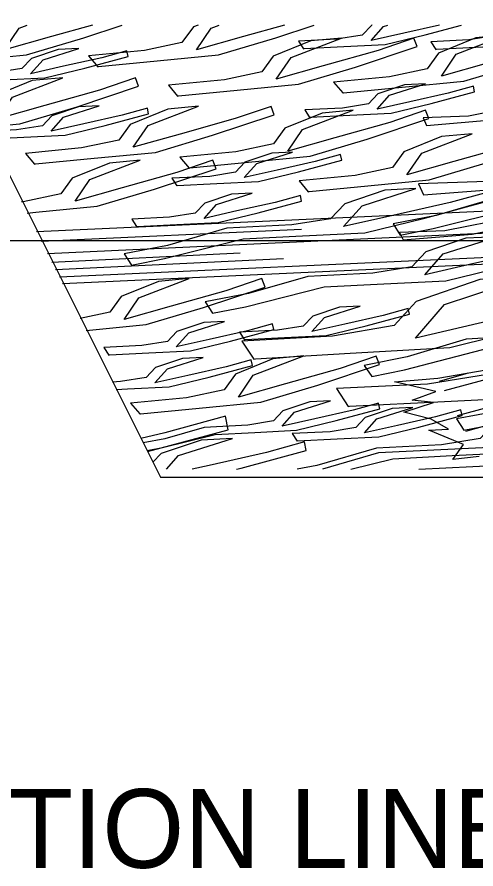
# Model space of a CAD drawing. Extents: x 1578769 to 1579225, y 724002 to 724828.
# Drawn here: x 1578874.36 to 1578877.28, y 724532.99 to 724538.4 of the extents above; entities that cross this region are included whole.
import ezdxf

# ---------------------------------------------------------------- set-up
doc = ezdxf.new("R2010")
doc.units = 0
for name, color, linetype in [('1', 7, 'Continuous'), ('G-ANNO-SYMB', 7, 'Continuous'), ('Old_Level_1', 7, 'Continuous'), ('Old_Level_41', 7, 'Continuous'), ('R_Fin Surface', 7, 'Continuous')]:
    doc.layers.add(name, color=color, linetype=linetype)

msp = doc.modelspace()

# ---------------------------------------------------------------- linework, layer by layer
at = {"layer": 'G-ANNO-SYMB'}
for p, q in [((1578877.0342, 724536.1057), (1578885.5756, 724537.5547)), ((1578874.4853, 724537.0347), (1578877.6371, 724537.1793)), ((1578874.5161, 724536.9737), (1578876.1682, 724537.0499)), ((1578874.5556, 724536.8955), (1578877.6246, 724537.0394)), ((1578874.5833, 724536.8408), (1578875.779, 724536.8994)), ((1578874.6065, 724536.7949), (1578876.0539, 724536.8636)), ((1578874.6306, 724536.7471), (1578877.5578, 724536.8825)), ((1578874.6516, 724536.7055), (1578877.5317, 724536.8379))]:
    msp.add_line(p, q, dxfattribs=at)
for points in [[(1578873.9421, 724538.1098), (1578874.033, 724538.1186), (1578874.4229, 724538.1563), (1578874.7854, 724538.2648), (1578875.0296, 724538.3458)], [(1578874.8405, 724538.3458), (1578874.5802, 724538.2725), (1578874.2817, 724538.1886), (1578874.3756, 724538.3263), (1578874.4264, 724538.3458)], [(1578875.511, 724538.3458), (1578875.4813, 724538.3337), (1578875.4091, 724538.2349), (1578875.1713, 724538.1843), (1578874.8157, 724538.15)], [(1578874.8157, 724538.15), (1578874.8742, 724538.081), (1578874.8796, 724538.0827), (1578875.2518, 724538.1186), (1578875.6417, 724538.1563), (1578876.0043, 724538.2648), (1578876.2485, 724538.3458)], [(1578876.0593, 724538.3458), (1578875.7991, 724538.2725), (1578875.5006, 724538.1886), (1578875.5944, 724538.3263), (1578875.6452, 724538.3458)], [(1578876.1497, 724538.2428), (1578876.1804, 724538.1953), (1578876.1842, 724538.1962), (1578876.4356, 724538.209), (1578876.699, 724538.2224), (1578876.9527, 724538.2836), (1578877.1825, 724538.3458)], [(1578876.616, 724538.3458), (1578876.6136, 724538.345), (1578876.5539, 724538.2815), (1578876.39, 724538.255), (1578876.1497, 724538.2428)], [(1578877.0436, 724538.3458), (1578876.8173, 724538.2949), (1578876.6091, 724538.248), (1578876.6879, 724538.3367), (1578876.7166, 724538.3458)], [(1578876.9894, 724538.239), (1578877.02, 724538.1914), (1578877.0238, 724538.1923), (1578877.2753, 724538.2051), (1578877.5387, 724538.2185), (1578877.7923, 724538.2797), (1578878.0365, 724538.3458)], [(1578877.4672, 724538.3458), (1578877.4533, 724538.3411), (1578877.3936, 724538.2776), (1578877.2296, 724538.2512), (1578876.9894, 724538.239)], [(1578876.3712, 724537.9835), (1578876.4297, 724537.9145), (1578876.4351, 724537.9162), (1578876.8073, 724537.9521), (1578877.1973, 724537.9898), (1578877.5598, 724538.0983), (1578877.9509, 724538.228), (1578877.9304, 724538.2811), (1578877.7028, 724538.204), (1578877.3546, 724538.1061), (1578877.0561, 724538.0221), (1578877.1499, 724538.1598), (1578877.4702, 724538.2826), (1578877.2752, 724538.2638), (1578877.0368, 724538.1672), (1578876.9646, 724538.0684), (1578876.7268, 724538.0178), (1578876.3712, 724537.9835)], [(1578875.3226, 724537.9641), (1578875.3811, 724537.8951), (1578875.3865, 724537.8968), (1578875.7587, 724537.9328), (1578876.1486, 724537.9704), (1578876.5112, 724538.079), (1578876.9023, 724538.2086), (1578876.8818, 724538.2618), (1578876.6542, 724538.1847), (1578876.306, 724538.0867), (1578876.0075, 724538.0027), (1578876.1013, 724538.1404), (1578876.4216, 724538.2633), (1578876.2266, 724538.2444), (1578875.9881, 724538.1479), (1578875.916, 724538.049), (1578875.6782, 724537.9985), (1578875.3226, 724537.9641)], [(1578873.9891, 724538.0317), (1578874.0197, 724537.9842), (1578874.0235, 724537.9851), (1578874.2749, 724537.9979), (1578874.5383, 724538.0113), (1578874.792, 724538.0725), (1578875.0672, 724538.1469), (1578875.0599, 724538.1829), (1578874.8996, 724538.1384), (1578874.6567, 724538.0838), (1578874.4484, 724538.0369), (1578874.5272, 724538.1256), (1578874.7545, 724538.1976), (1578874.6228, 724538.1909), (1578874.4529, 724538.1339), (1578874.3933, 724538.0704), (1578874.2293, 724538.0439), (1578873.9891, 724538.0317)], [(1578874.1509, 724537.6966), (1578874.3803, 724537.7188), (1578874.7429, 724537.8273), (1578875.134, 724537.957), (1578875.1135, 724538.0101), (1578874.8859, 724537.933), (1578874.5376, 724537.835), (1578874.2391, 724537.7511), (1578874.333, 724537.8888), (1578874.6533, 724538.0116), (1578874.4583, 724537.9928), (1578874.2198, 724537.8962), (1578874.1477, 724537.7974), (1578874.1046, 724537.7882)], [(1578876.1887, 724537.807), (1578876.2193, 724537.7594), (1578876.2231, 724537.7604), (1578876.4745, 724537.7732), (1578876.7379, 724537.7865), (1578876.9916, 724537.8478), (1578877.2668, 724537.9222), (1578877.2595, 724537.9581), (1578877.0992, 724537.9137), (1578876.8563, 724537.859), (1578876.648, 724537.8122), (1578876.7268, 724537.9008), (1578876.9541, 724537.9728), (1578876.8224, 724537.9661), (1578876.6525, 724537.9091), (1578876.5929, 724537.8457), (1578876.4289, 724537.8192), (1578876.1887, 724537.807)], [(1578874.1881, 724537.6228), (1578874.4044, 724537.6338), (1578874.6678, 724537.6471), (1578874.9215, 724537.7084), (1578875.1967, 724537.7828), (1578875.1894, 724537.8187), (1578875.029, 724537.7743), (1578874.7861, 724537.7197), (1578874.5779, 724537.6728), (1578874.6567, 724537.7614), (1578874.884, 724537.8334), (1578874.7523, 724537.8268), (1578874.5824, 724537.7698), (1578874.5227, 724537.7063), (1578874.3588, 724537.6798), (1578874.1643, 724537.6699)], [(1578874.4151, 724537.5313), (1578874.4736, 724537.4623), (1578874.479, 724537.464), (1578874.8512, 724537.4999), (1578875.2411, 724537.5376), (1578875.6037, 724537.6461), (1578875.9948, 724537.7758), (1578875.9743, 724537.8289), (1578875.7467, 724537.7518), (1578875.3984, 724537.6539), (1578875.1, 724537.5699), (1578875.1938, 724537.7076), (1578875.5141, 724537.8304), (1578875.3191, 724537.8116), (1578875.0806, 724537.715), (1578875.0085, 724537.6162), (1578874.7707, 724537.5656), (1578874.4151, 724537.5313)], [(1578875.3961, 724537.5073), (1578875.4546, 724537.4382), (1578875.46, 724537.4399), (1578875.8322, 724537.4759), (1578876.2222, 724537.5135), (1578876.5847, 724537.6221), (1578876.9758, 724537.7517), (1578876.9553, 724537.8049), (1578876.7277, 724537.7278), (1578876.3795, 724537.6298), (1578876.081, 724537.5459), (1578876.1749, 724537.6836), (1578876.4951, 724537.8064), (1578876.3001, 724537.7875), (1578876.0617, 724537.691), (1578875.9896, 724537.5922), (1578875.7517, 724537.5416), (1578875.3961, 724537.5073)], [(1578876.1524, 724537.3571), (1578876.211, 724537.2881), (1578876.2164, 724537.2897), (1578876.5886, 724537.3257), (1578876.9785, 724537.3634), (1578877.341, 724537.4719), (1578877.7322, 724537.6016), (1578877.7117, 724537.6547), (1578877.4841, 724537.5776), (1578877.1358, 724537.4796), (1578876.8373, 724537.3957), (1578876.9312, 724537.5334), (1578877.2514, 724537.6562), (1578877.0565, 724537.6374), (1578876.818, 724537.5408), (1578876.7459, 724537.442), (1578876.508, 724537.3914), (1578876.1524, 724537.3571)], [(1578875.3451, 724537.3733), (1578875.3758, 724537.3258), (1578875.3796, 724537.3267), (1578875.631, 724537.3395), (1578875.8944, 724537.3529), (1578876.1481, 724537.4141), (1578876.4233, 724537.4886), (1578876.416, 724537.5245), (1578876.2556, 724537.48), (1578876.0127, 724537.4254), (1578875.8045, 724537.3785), (1578875.8833, 724537.4672), (1578876.1106, 724537.5392), (1578875.9789, 724537.5325), (1578875.809, 724537.4755), (1578875.7493, 724537.412), (1578875.5854, 724537.3855), (1578875.3451, 724537.3733)], [(1578874.4255, 724537.153), (1578874.4818, 724537.1584), (1578874.8717, 724537.1961), (1578875.2343, 724537.3046), (1578875.6254, 724537.4343), (1578875.6049, 724537.4874), (1578875.3773, 724537.4103), (1578875.029, 724537.3123), (1578874.7306, 724537.2284), (1578874.8244, 724537.3661), (1578875.1447, 724537.4889), (1578874.9497, 724537.4701), (1578874.7112, 724537.3735), (1578874.6391, 724537.2747), (1578874.4013, 724537.2241), (1578874.3901, 724537.223)], [(1578876.749, 724537.0847), (1578876.7952, 724537.013), (1578877.0036, 724537.0545), (1578877.5043, 724537.1797), (1578877.8815, 724537.1989), (1578878.2766, 724537.2189), (1578878.6571, 724537.3108), (1578879.0699, 724537.4224), (1578879.0589, 724537.4763), (1578878.8184, 724537.4097), (1578878.4541, 724537.3277), (1578878.1418, 724537.2574), (1578878.2599, 724537.3904), (1578878.6008, 724537.4984), (1578878.4033, 724537.4883), (1578878.1485, 724537.4028), (1578878.059, 724537.3076), (1578877.813, 724537.2679), (1578877.4, 724537.2469), (1578877.0231, 724537.1371), (1578876.749, 724537.0847)], [(1578875.0426, 724536.8938), (1578875.0888, 724536.8221), (1578875.2972, 724536.8636), (1578875.798, 724536.9888), (1578876.1751, 724537.008), (1578876.5702, 724537.028), (1578876.9507, 724537.1199), (1578877.3635, 724537.2315), (1578877.3526, 724537.2854), (1578877.1121, 724537.2188), (1578876.7477, 724537.1368), (1578876.4354, 724537.0665), (1578876.5535, 724537.1995), (1578876.8945, 724537.3075), (1578876.6969, 724537.2974), (1578876.4421, 724537.212), (1578876.3526, 724537.1167), (1578876.1067, 724537.077), (1578875.6936, 724537.056), (1578875.3167, 724536.9462), (1578875.0426, 724536.8938)], [(1578875.0898, 724537.1139), (1578875.1204, 724537.0664), (1578875.1242, 724537.0673), (1578875.3756, 724537.0801), (1578875.639, 724537.0935), (1578875.8927, 724537.1547), (1578876.1679, 724537.2291), (1578876.1606, 724537.265), (1578876.0003, 724537.2206), (1578875.7573, 724537.166), (1578875.5491, 724537.1191), (1578875.6279, 724537.2078), (1578875.8552, 724537.2798), (1578875.7235, 724537.2731), (1578875.5536, 724537.2161), (1578875.4939, 724537.1526), (1578875.33, 724537.1261), (1578875.0898, 724537.1139)], [(1578875.5573, 724536.5889), (1578875.6035, 724536.5172), (1578875.8119, 724536.5587), (1578876.3126, 724536.6839), (1578876.6898, 724536.703), (1578877.0849, 724536.7231), (1578877.4654, 724536.815), (1578877.8782, 724536.9266), (1578877.8672, 724536.9805), (1578877.6267, 724536.9139), (1578877.2624, 724536.8319), (1578876.95, 724536.7616), (1578877.0682, 724536.8946), (1578877.4091, 724537.0026), (1578877.2116, 724536.9925), (1578876.9568, 724536.907), (1578876.8673, 724536.8118), (1578876.6213, 724536.7721), (1578876.2082, 724536.7511), (1578875.8314, 724536.6413), (1578875.5573, 724536.5889)], [(1578874.8018, 724536.4083), (1578875.1828, 724536.4451), (1578875.5453, 724536.5536), (1578875.9365, 724536.6833), (1578875.9159, 724536.7364), (1578875.6883, 724536.6593), (1578875.3401, 724536.5614), (1578875.0416, 724536.4774), (1578875.1355, 724536.6151), (1578875.4557, 724536.7379), (1578875.2608, 724536.7191), (1578875.0223, 724536.6225), (1578874.9502, 724536.5237), (1578874.7635, 724536.484)], [(1578875.7893, 724536.3396), (1578875.8657, 724536.2259), (1578875.8748, 724536.2282), (1578876.4774, 724536.2628), (1578877.1087, 724536.2989), (1578877.7137, 724536.4498), (1578878.3695, 724536.6327), (1578878.3498, 724536.7187), (1578877.9678, 724536.6097), (1578877.3882, 724536.4748), (1578876.8914, 724536.3591), (1578877.0749, 724536.5731), (1578877.616, 724536.7493), (1578877.3003, 724536.7313), (1578876.8962, 724536.5919), (1578876.7569, 724536.4386), (1578876.365, 724536.3726), (1578875.7893, 724536.3396)], [(1578876.5656, 724536.1865), (1578876.6136, 724536.115), (1578876.8209, 724536.1579), (1578877.3184, 724536.2863), (1578877.6951, 724536.3079), (1578878.0896, 724536.3305), (1578878.4677, 724536.4248), (1578878.8776, 724536.5391), (1578878.8653, 724536.5929), (1578878.6265, 724536.5247), (1578878.2643, 724536.4404), (1578877.9538, 724536.3681), (1578878.0685, 724536.5018), (1578878.4067, 724536.612), (1578878.2094, 724536.6007), (1578877.9568, 724536.5136), (1578877.8697, 724536.4178), (1578877.6248, 724536.3765), (1578877.2123, 724536.3529), (1578876.8383, 724536.2406), (1578876.5656, 724536.1865)], [(1578875.7751, 724536.3966), (1578875.8057, 724536.349), (1578875.8095, 724536.35), (1578876.0609, 724536.3627), (1578876.3243, 724536.3761), (1578876.578, 724536.4374), (1578876.8532, 724536.5118), (1578876.8459, 724536.5477), (1578876.6856, 724536.5033), (1578876.4427, 724536.4486), (1578876.2344, 724536.4018), (1578876.3132, 724536.4904), (1578876.5405, 724536.5624), (1578876.4088, 724536.5557), (1578876.2389, 724536.4987), (1578876.1793, 724536.4352), (1578876.0153, 724536.4088), (1578875.7751, 724536.3966)], [(1578877.1581, 724535.8691), (1578877.9126, 724536.073), (1578878.518, 724536.213), (1578878.8249, 724536.3238), (1578879.0076, 724536.3655), (1578879.3403, 724536.4158), (1578879.5398, 724536.4872)], [(1578874.9136, 724536.2993), (1578874.9442, 724536.2517), (1578874.948, 724536.2527), (1578875.1994, 724536.2654), (1578875.4628, 724536.2788), (1578875.7165, 724536.3401), (1578875.9917, 724536.4145), (1578875.9844, 724536.4504), (1578875.8241, 724536.406), (1578875.5811, 724536.3513), (1578875.3729, 724536.3045), (1578875.4517, 724536.3931), (1578875.679, 724536.4651), (1578875.5473, 724536.4584), (1578875.3774, 724536.4014), (1578875.3177, 724536.338), (1578875.1538, 724536.3115), (1578874.9136, 724536.2993)], [(1578876.3905, 724536.0387), (1578876.464, 724535.9246), (1578876.4731, 724535.9268), (1578877.0766, 724535.9575), (1578877.7087, 724535.9896), (1578878.3175, 724536.1366), (1578878.978, 724536.3152), (1578878.9605, 724536.4014), (1578878.5757, 724536.2948), (1578877.9927, 724536.1636), (1578877.493, 724536.0512), (1578877.682, 724536.2639), (1578878.2275, 724536.4367), (1578877.9115, 724536.4207), (1578877.5038, 724536.2839), (1578877.3605, 724536.1315), (1578876.967, 724536.068), (1578876.3905, 724536.0387)], [(1578877.2106, 724535.769), (1578877.7614, 724535.9235), (1578878.6223, 724536.1425), (1578878.9606, 724536.2065), (1578879.6231, 724536.3903)], [(1578874.9913, 724536.0333), (1578875.064, 724536.037), (1578875.3274, 724536.0504), (1578875.5811, 724536.1116), (1578875.8563, 724536.1861), (1578875.849, 724536.222), (1578875.6886, 724536.1775), (1578875.4457, 724536.1229), (1578875.2375, 724536.076), (1578875.3163, 724536.1647), (1578875.5436, 724536.2367), (1578875.4119, 724536.23), (1578875.242, 724536.173), (1578875.1823, 724536.1095), (1578875.0183, 724536.0831), (1578874.9674, 724536.0805)], [(1578875.0827, 724535.9469), (1578875.1412, 724535.8779), (1578875.1466, 724535.8796), (1578875.5188, 724535.9155), (1578875.9087, 724535.9532), (1578876.2713, 724536.0617), (1578876.6624, 724536.1914), (1578876.6419, 724536.2445), (1578876.4143, 724536.1674), (1578876.066, 724536.0695), (1578875.7676, 724535.9855), (1578875.8614, 724536.1232), (1578876.1817, 724536.246), (1578875.9867, 724536.2272), (1578875.7482, 724536.1306), (1578875.6761, 724536.0318), (1578875.4383, 724535.9812), (1578875.0827, 724535.9469)], [(1578877.1522, 724535.8462), (1578877.1984, 724535.7744), (1578877.4068, 724535.816), (1578877.9076, 724535.9411), (1578878.2847, 724535.9603), (1578878.6798, 724535.9804), (1578879.0603, 724536.0722), (1578879.4731, 724536.1839), (1578879.4622, 724536.2377), (1578879.2217, 724536.1711), (1578878.8573, 724536.0891), (1578878.545, 724536.0188), (1578878.6631, 724536.1518), (1578879.0041, 724536.2598), (1578878.8065, 724536.2498), (1578878.5517, 724536.1643), (1578878.4622, 724536.0691), (1578878.2163, 724536.0294), (1578877.8032, 724536.0084), (1578877.4263, 724535.8986), (1578877.1522, 724535.8462)], [(1578875.1874, 724535.6451), (1578875.2865, 724535.6649), (1578875.6204, 724535.7483), (1578875.8718, 724535.7611), (1578876.1352, 724535.7745), (1578876.3889, 724535.8357), (1578876.6641, 724535.9101), (1578876.6568, 724535.946), (1578876.4964, 724535.9016), (1578876.2535, 724535.847), (1578876.0453, 724535.8001), (1578876.1241, 724535.8888), (1578876.3514, 724535.9608), (1578876.2197, 724535.9541), (1578876.0498, 724535.8971), (1578875.9901, 724535.8336), (1578875.8262, 724535.8071), (1578875.5508, 724535.7931), (1578875.2995, 724535.7199), (1578875.1628, 724535.6938)], [(1578876.1088, 724535.7532), (1578876.1394, 724535.7056), (1578876.1432, 724535.7066), (1578876.3947, 724535.7193), (1578876.6581, 724535.7327), (1578876.9117, 724535.794), (1578877.1869, 724535.8684), (1578877.1796, 724535.9043), (1578877.0193, 724535.8599), (1578876.7764, 724535.8052), (1578876.5682, 724535.7584), (1578876.6469, 724535.847), (1578876.8742, 724535.919), (1578876.7425, 724535.9123), (1578876.5727, 724535.8553), (1578876.513, 724535.7918), (1578876.349, 724535.7654), (1578876.1088, 724535.7532)], [(1578876.4805, 724535.5275), (1578876.7474, 724535.5942), (1578877.1245, 724535.6134), (1578877.5196, 724535.6334), (1578877.9001, 724535.7253), (1578878.3129, 724535.837), (1578878.302, 724535.8908), (1578878.0615, 724535.8242), (1578877.6971, 724535.7422), (1578877.3848, 724535.6719), (1578877.5029, 724535.8049), (1578877.8439, 724535.9129), (1578877.6463, 724535.9028), (1578877.3915, 724535.8174), (1578877.302, 724535.7221), (1578877.0561, 724535.6824), (1578876.643, 724535.6615), (1578876.2662, 724535.5516), (1578876.1397, 724535.5275)], [(1578875.1904, 724535.6392), (1578875.7027, 724535.7777), (1578875.6852, 724535.8639), (1578875.3004, 724535.7573), (1578875.148, 724535.723)], [(1578875.3106, 724535.5274), (1578875.3879, 724535.6143), (1578875.7288, 724535.7223), (1578875.5313, 724535.7123), (1578875.2765, 724535.6268), (1578875.2246, 724535.5716)], [(1578875.7548, 724535.5274), (1578875.7851, 724535.5347), (1578876.1978, 724535.6464), (1578876.1869, 724535.7002), (1578875.9464, 724535.6336), (1578875.582, 724535.5516), (1578875.4744, 724535.5274)]]:
    msp.add_lwpolyline(points, dxfattribs=at)
for points in [[(1578876.9622, 724537.7091), (1578877.4018, 724537.7464), (1578877.6447, 724537.7967), (1578877.9763, 724537.8823), (1578878.2274, 724537.8966), (1578878.4904, 724537.9117), (1578878.7425, 724537.9746), (1578879.0158, 724538.0508), (1578879.0075, 724538.0866), (1578878.8484, 724538.0412), (1578878.6069, 724537.985), (1578878.3999, 724537.9368), (1578878.4764, 724538.0259), (1578878.7018, 724538.0994), (1578878.5703, 724538.0918), (1578878.4019, 724538.0338), (1578878.3438, 724537.9699), (1578878.1806, 724537.9424), (1578877.9056, 724537.9266), (1578877.6562, 724537.8518), (1578877.2276, 724537.7667), (1578876.9392, 724537.7563)], [(1578876.9425, 724537.2681), (1578877.6034, 724537.3198), (1578877.9695, 724537.3928), (1578878.4703, 724537.518), (1578878.8474, 724537.5371), (1578879.2425, 724537.5572), (1578879.623, 724537.6491), (1578880.0358, 724537.7607), (1578880.0249, 724537.8146), (1578879.7844, 724537.7479), (1578879.42, 724537.666), (1578879.1077, 724537.5957), (1578879.2259, 724537.7286), (1578879.5668, 724537.8366), (1578879.3692, 724537.8266), (1578879.1145, 724537.7411), (1578879.0249, 724537.6459), (1578878.779, 724537.6062), (1578878.3659, 724537.5852), (1578877.9891, 724537.4754), (1578877.3428, 724537.3519), (1578876.91, 724537.339)], [(1578876.8122, 724536.9819), (1578877.2519, 724537.0192), (1578877.4947, 724537.0694), (1578877.8264, 724537.155), (1578878.0775, 724537.1694), (1578878.3405, 724537.1845), (1578878.5926, 724537.2473), (1578878.8658, 724537.3235), (1578878.8576, 724537.3594), (1578878.6984, 724537.3139), (1578878.457, 724537.2577), (1578878.25, 724537.2095), (1578878.3264, 724537.2987), (1578878.5519, 724537.3721), (1578878.4204, 724537.3646), (1578878.252, 724537.3065), (1578878.1939, 724537.2427), (1578878.0306, 724537.2151), (1578877.7557, 724537.1994), (1578877.5063, 724537.1246), (1578877.0776, 724537.0395), (1578876.7893, 724537.029)]]:
    msp.add_lwpolyline(points, close=True, dxfattribs=at)
at = {"layer": 'Old_Level_1'}
for p, q in [((1578876.7588, 724536.0812), (1578877.0342, 724536.1057)), ((1578877.0203, 724536.0196), (1578876.7588, 724536.0812)), ((1578876.8695, 724535.966), (1578877.0203, 724536.0196)), ((1578876.8178, 724535.8889), (1578877.0053, 724535.95)), ((1578877.0053, 724535.95), (1578876.8695, 724535.966)), ((1578876.9903, 724535.8458), (1578876.8178, 724535.8889)), ((1578877.1004, 724535.7825), (1578876.9903, 724535.8458)), ((1578876.9753, 724535.7761), (1578877.1004, 724535.7825)), ((1578877.1957, 724535.6834), (1578876.9753, 724535.7761)), ((1578877.1279, 724535.5886), (1578877.1957, 724535.6834)), ((1578877.2949, 724535.608), (1578877.1279, 724535.5886))]:
    msp.add_line(p, q, dxfattribs=at)
at = {"layer": 'Old_Level_41'}
for points in [[(1578927.7658, 724536.9761), (1578827.7658, 724536.9761)], [(1578877.0754, 724536.0272), (1578877.5384, 724536.1525), (1578877.6755, 724536.1761), (1578877.7611, 724536.1679), (1578878.2333, 724536.2787), (1578878.4013, 724536.3376)], [(1578877.0441, 724536.0868), (1578877.2128, 724536.1346), (1578877.2266, 724536.1383)], [(1578876.9128, 724535.5275), (1578877.4261, 724535.5536), (1578878.0583, 724535.5857), (1578878.6671, 724535.7327), (1578879.3276, 724535.9113), (1578879.3101, 724535.9975), (1578878.9253, 724535.8909), (1578878.3423, 724535.7597), (1578877.8426, 724535.6473), (1578878.0316, 724535.86), (1578878.5771, 724536.0328), (1578878.261, 724536.0168), (1578877.8534, 724535.88), (1578877.7101, 724535.7276), (1578877.3166, 724535.6641), (1578876.6557, 724535.6305), (1578876.3021, 724535.5275)]]:
    msp.add_lwpolyline(points, dxfattribs=at)
at = {"layer": 'R_Fin Surface'}
msp.add_line((1578873.2745, 724539.467), (1578875.2728, 724535.4761), dxfattribs=at)
msp.add_line((1578873.2745, 724539.467), (1578875.2728, 724535.4761), dxfattribs=at)
msp.add_lwpolyline([(1578875.2728, 724535.4761), (1578888.441, 724535.4761)], dxfattribs=at)
msp.add_lwpolyline([(1578875.2728, 724535.4761), (1578888.441, 724535.4761)], dxfattribs=at)

# ---------------------------------------------------------------- texts
at = {"layer": '1'}
msp.add_text('EXCAVATION LINE', height=0.5, dxfattribs=at).set_placement((1578871.5965, 724532.9982))

doc.saveas('drawing.dxf')
